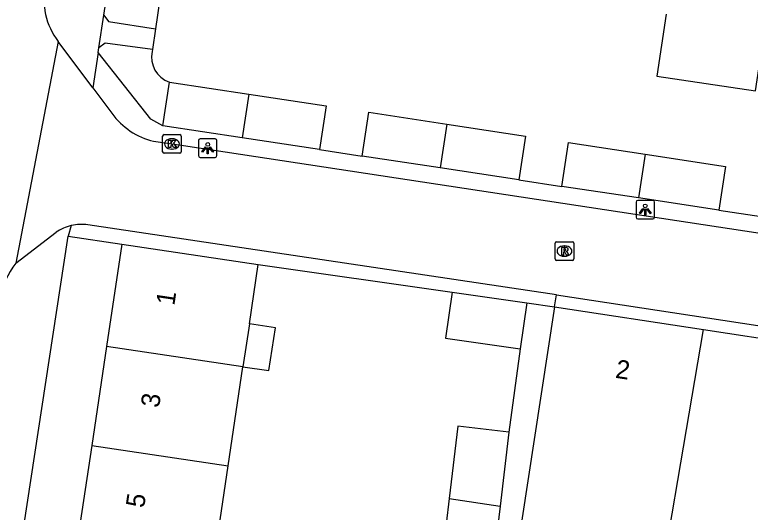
# Model space of a CAD drawing. Extents: x 163010 to 163853, y 382793 to 383982.
# Drawn here: x 163538.3 to 163577.85, y 383156.8 to 383183.57 of the extents above; entities that cross this region are included whole.
import ezdxf

# ---------------------------------------------------------------- set-up
doc = ezdxf.new("R2010")
doc.units = 0
for name, color, linetype in [('IMGEO_Groenvoorziening', 7, 'Continuous'), ('IMGEO_Kolk', 7, 'Continuous'), ('IMGEO_Lichtpunt', 7, 'Continuous'), ('IMGEO_Muur', 7, 'Continuous'), ('IMGEO_Pand', 7, 'Continuous'), ('IMGEO_Pand_nummerreeks', 7, 'Continuous'), ('IMGEO_Rijbaan_lokaal_open', 7, 'Continuous'), ('IMGEO_Rioolput', 7, 'Continuous'), ('IMGEO_Voetpad_open', 7, 'Continuous')]:
    doc.layers.add(name, color=color, linetype=linetype)

msp = doc.modelspace()

# ---------------------------------------------------------------- linework, layer by layer
at = {"layer": 'IMGEO_Groenvoorziening'}
for points in [[(163546.582, 383187.748), (163545.87, 383182.817)], [(163545.709, 383181.698), (163545.693, 383181.587)]]:
    msp.add_lwpolyline(points, dxfattribs=at)
msp.add_arc((163547.06, 383181.277), 1.401, 167.2093, 251.4564, dxfattribs=at)
at = {"layer": 'IMGEO_Kolk'}
for p, q in [((163546.326, 383177.12), (163547.178, 383177.12)), ((163546.251, 383176.194), (163546.251, 383177.046)), ((163546.739, 383176.9), (163546.764, 383176.9)), ((163547.252, 383177.046), (163547.252, 383176.194)), ((163546.762, 383176.34), (163546.737, 383176.34)), ((163547.178, 383176.12), (163546.326, 383176.12))]:
    msp.add_line(p, q, dxfattribs=at)
for points in [[(163546.326, 383177.12), (163547.178, 383177.12)], [(163546.251, 383176.194), (163546.251, 383177.046)], [(163546.572, 383176.82), (163546.695, 383176.82), (163546.695, 383176.669), (163546.825, 383176.82), (163546.989, 383176.82), (163546.843, 383176.669), (163546.996, 383176.42), (163546.844, 383176.42), (163546.759, 383176.584), (163546.695, 383176.517), (163546.695, 383176.42), (163546.572, 383176.42), (163546.572, 383176.82)], [(163547.252, 383177.046), (163547.252, 383176.194)], [(163547.178, 383176.12), (163546.326, 383176.12)]]:
    msp.add_lwpolyline(points, dxfattribs=at)
for centre, start, end in [((163546.328, 383177.044), 91.552, 178.448), ((163546.328, 383177.044), 91.552, 178.448), ((163547.176, 383177.044), 1.552, 88.448), ((163547.176, 383177.044), 1.552, 88.448), ((163546.328, 383176.196), 181.552, 268.448), ((163546.328, 383176.196), 181.552, 268.448), ((163547.176, 383176.196), 271.552, 358.448), ((163547.176, 383176.196), 271.552, 358.448)]:
    msp.add_arc(centre, 0.0765, start, end, dxfattribs=at)
for centre, major_axis, ratio, start_param, end_param in [((163546.738, 383176.62), (-0.387, 0.002), 0.722429, 4.712389, 7.853982), ((163546.763, 383176.62), (-0.39, 0.002), 0.717154, 1.570796, 4.712389)]:
    msp.add_ellipse(centre, major_axis=major_axis, ratio=ratio, start_param=start_param, end_param=end_param, dxfattribs=at)
at = {"layer": 'IMGEO_Lichtpunt'}
for p, q in [((163548.177, 383176.796), (163548.177, 383175.989)), ((163548.177, 383176.796), (163548.177, 383175.989)), ((163549.079, 383176.891), (163548.271, 383176.891)), ((163549.079, 383176.891), (163548.271, 383176.891)), ((163549.173, 383175.989), (163549.173, 383176.796)), ((163549.173, 383175.989), (163549.173, 383176.796)), ((163548.271, 383175.895), (163549.079, 383175.895)), ((163548.271, 383175.895), (163549.079, 383175.895)), ((163572.609, 383173.582), (163571.801, 383173.582)), ((163572.609, 383173.582), (163571.801, 383173.582)), ((163571.707, 383173.487), (163571.707, 383172.68)), ((163571.707, 383173.487), (163571.707, 383172.68)), ((163572.703, 383172.68), (163572.703, 383173.487)), ((163572.703, 383172.68), (163572.703, 383173.487)), ((163571.801, 383172.586), (163572.609, 383172.586)), ((163571.801, 383172.586), (163572.609, 383172.586))]:
    msp.add_line(p, q, dxfattribs=at)
for points in [[(163548.551, 383176.46), (163548.59, 383176.432), (163548.402, 383176.17), (163548.364, 383176.197), (163548.551, 383176.46)], [(163548.653, 383176.412), (163548.7, 383176.412), (163548.7, 383176.09), (163548.653, 383176.09), (163548.653, 383176.412)], [(163548.763, 383176.432), (163548.801, 383176.459), (163548.988, 383176.197), (163548.949, 383176.169), (163548.763, 383176.432)], [(163572.081, 383173.151), (163572.12, 383173.123), (163571.932, 383172.861), (163571.894, 383172.888), (163572.081, 383173.151)], [(163572.293, 383173.123), (163572.331, 383173.15), (163572.518, 383172.888), (163572.479, 383172.86), (163572.293, 383173.123)], [(163572.183, 383173.103), (163572.23, 383173.103), (163572.23, 383172.781), (163572.183, 383172.781), (163572.183, 383173.103)]]:
    msp.add_lwpolyline(points, dxfattribs=at)
for centre in [(163548.676, 383176.594), (163572.206, 383173.285)]:
    msp.add_circle(centre, 0.0994, dxfattribs=at)
for centre, start, end in [((163548.271, 383176.796), 90, 180), ((163548.271, 383176.796), 90, 180), ((163549.079, 383176.796), 0, 90), ((163549.079, 383176.796), 0, 90), ((163548.271, 383175.989), 180, 270), ((163548.271, 383175.989), 180, 270), ((163549.079, 383175.989), 270, 0), ((163549.079, 383175.989), 270, 360), ((163571.801, 383173.487), 90, 180), ((163571.801, 383173.487), 90, 180), ((163572.609, 383173.487), 0, 90), ((163572.609, 383173.487), 0, 90), ((163571.801, 383172.68), 180, 270), ((163571.801, 383172.68), 180, 270), ((163572.609, 383172.68), 270, 0), ((163572.609, 383172.68), 270, 360)]:
    msp.add_arc(centre, 0.0946, start, end, dxfattribs=at)
at = {"layer": 'IMGEO_Muur'}
msp.add_lwpolyline([(163551.396, 383170.138), (163561.824, 383168.644)], dxfattribs=at)
at = {"layer": 'IMGEO_Pand'}
for points in [[(163573.324, 383183.6), (163572.822, 383180.27), (163578.138, 383179.469), (163578.64, 383182.799)], [(163546.258, 383177.595), (163546.614, 383179.948)], [(163546.614, 383179.948), (163550.881, 383179.3)], [(163550.881, 383179.3), (163550.526, 383176.947)], [(163550.881, 383179.3), (163555.039, 383178.669), (163554.681, 383176.317)], [(163556.975, 383175.968), (163557.333, 383178.321), (163561.536, 383177.683)], [(163550.526, 383176.947), (163546.258, 383177.595)], [(163561.536, 383177.683), (163561.181, 383175.33)], [(163561.536, 383177.683), (163565.767, 383177.041), (163565.409, 383174.688)], [(163554.681, 383176.317), (163550.526, 383176.947)], [(163567.712, 383174.339), (163568.07, 383176.691), (163572.191, 383176.066)], [(163561.181, 383175.33), (163556.975, 383175.968)], [(163572.191, 383176.066), (163571.836, 383173.713)], [(163572.191, 383176.066), (163576.523, 383175.409), (163576.165, 383173.056)], [(163565.409, 383174.688), (163561.181, 383175.33)], [(163571.836, 383173.713), (163567.712, 383174.339)], [(163576.165, 383173.056), (163571.836, 383173.713)], [(163544.062, 383171.234), (163543.239, 383165.731)], [(163544.062, 383171.234), (163551.396, 383170.138)], [(163550.917, 383166.934), (163551.396, 383170.138)], [(163561.824, 383168.644), (163561.47, 383166.171), (163565.479, 383165.596)], [(163561.824, 383168.644), (163565.833, 383168.07)], [(163565.833, 383168.07), (163565.479, 383165.596)], [(163567.317, 383167.857), (163564.835, 383151.595), (163572.264, 383148.601)], [(163567.317, 383167.857), (163575.341, 383166.634)], [(163550.917, 383166.934), (163550.573, 383164.635)], [(163550.573, 383164.635), (163551.969, 383164.426), (163552.313, 383166.725), (163550.917, 383166.934)], [(163572.264, 383148.601), (163575.341, 383166.634)], [(163575.341, 383166.634), (163590.125, 383164.381)], [(163543.239, 383165.731), (163542.443, 383160.401)], [(163550.573, 383164.635), (163543.239, 383165.731)], [(163549.777, 383159.305), (163550.573, 383164.635)], [(163564.869, 383161.116), (163562.127, 383161.441), (163561.665, 383157.549)], [(163564.869, 383161.116), (163564.397, 383157.141)], [(163542.443, 383160.401), (163541.646, 383155.072)], [(163542.443, 383160.401), (163549.777, 383159.305)], [(163548.98, 383153.976), (163549.777, 383159.305)], [(163561.665, 383157.549), (163561.18, 383153.465), (163563.922, 383153.139)], [(163561.665, 383157.549), (163564.397, 383157.141)], [(163564.397, 383157.141), (163563.922, 383153.139)]]:
    msp.add_lwpolyline(points, dxfattribs=at)
at = {"layer": 'IMGEO_Rijbaan_lokaal_open'}
for points in [[(163540.639, 383182.128), (163538.367, 383170.199)], [(163542.503, 383179.637), (163540.639, 383182.128)], [(163542.503, 383179.637), (163543.527, 383178.267)], [(163545.77, 383176.763), (163547.368, 383176.527), (163662.219, 383159.074)], [(163567.427, 383168.507), (163542.236, 383172.265)], [(163538.367, 383170.199), (163540.525, 383171.865)], [(163567.427, 383168.507), (163651.335, 383155.72)]]:
    msp.add_lwpolyline(points, dxfattribs=at)
for centre, radius, start, end in [((163543.66, 383184.425), 3.795, 168.4871, 217.2527), ((163546.659, 383180.513), 3.854, 215.6501, 256.6638), ((163541.883, 383169.929), 2.365, 103.2213, 125.0416), ((163541.877, 383169.947), 2.346, 81.1849, 103.171), ((163541.561, 383167.616), 4.108, 141.0286, 170.7761)]:
    msp.add_arc(centre, radius, start, end, dxfattribs=at)
at = {"layer": 'IMGEO_Rioolput'}
for p, q in [((163567.359, 383170.431), (163567.359, 383171.283)), ((163567.434, 383171.357), (163568.286, 383171.357)), ((163568.36, 383171.283), (163568.36, 383170.431)), ((163567.847, 383171.137), (163567.872, 383171.137)), ((163567.87, 383170.577), (163567.845, 383170.577)), ((163568.286, 383170.357), (163567.434, 383170.357))]:
    msp.add_line(p, q, dxfattribs=at)
for points in [[(163567.359, 383170.431), (163567.359, 383171.283)], [(163567.434, 383171.357), (163568.286, 383171.357)], [(163568.36, 383171.283), (163568.36, 383170.431)], [(163567.948, 383171.055), (163567.696, 383171.057), (163567.696, 383170.657)], [(163567.696, 383170.657), (163567.82, 383170.657), (163567.82, 383170.819), (163567.831, 383170.819)], [(163567.874, 383170.976), (163567.82, 383170.976), (163567.82, 383170.895)], [(163567.82, 383170.895), (163567.872, 383170.895)], [(163567.878, 383170.79), (163567.949, 383170.657), (163568.089, 383170.657), (163568.024, 383170.783)], [(163568.286, 383170.357), (163567.434, 383170.357)]]:
    msp.add_lwpolyline(points, dxfattribs=at)
for centre, radius, start, end in [((163567.436, 383171.281), 0.0765, 91.552, 178.448), ((163567.436, 383171.281), 0.0765, 91.552, 178.448), ((163568.284, 383171.281), 0.0765, 1.552, 88.448), ((163568.284, 383171.281), 0.0765, 1.552, 88.448), ((163567.83, 383170.766), 0.0533, 26.0293, 88.6989), ((163567.856, 383171.084), 0.19, 274.7715, 282.9687), ((163567.88, 383170.88), 0.0964, 77.0061, 93.1865), ((163567.894, 383170.937), 0.0378, 276.6634, 79.6772), ((163567.947, 383170.945), 0.109, 350.3612, 89.416), ((163567.945, 383170.945), 0.112, 277.5842, 350.9817), ((163567.929, 383170.73), 0.108, 29.5134, 73.7905), ((163567.436, 383170.433), 0.0765, 181.552, 268.448), ((163567.436, 383170.433), 0.0765, 181.552, 268.448), ((163568.284, 383170.433), 0.0765, 271.552, 358.448), ((163568.284, 383170.433), 0.0765, 271.552, 358.448)]:
    msp.add_arc(centre, radius, start, end, dxfattribs=at)
for centre, major_axis, ratio, start_param, end_param in [((163567.846, 383170.857), (-0.387, 0.002), 0.722429, 4.712389, 7.853982), ((163567.871, 383170.857), (-0.39, 0.002), 0.717154, 1.570796, 4.712389)]:
    msp.add_ellipse(centre, major_axis=major_axis, ratio=ratio, start_param=start_param, end_param=end_param, dxfattribs=at)
at = {"layer": 'IMGEO_Voetpad_open'}
for points in [[(163543.097, 383183.543), (163545.516, 383199.393)], [(163542.828, 383181.785), (163543.097, 383183.543)], [(163543.097, 383183.543), (163543.349, 383183.201), (163545.87, 383182.817)], [(163545.87, 383182.817), (163545.709, 383181.698)], [(163545.709, 383181.698), (163543.165, 383182.037), (163542.828, 383181.785)], [(163542.791, 383181.541), (163542.503, 383179.637)], [(163542.791, 383181.541), (163542.828, 383181.785)], [(163546.258, 383177.595), (163545.615, 383177.956), (163542.791, 383181.541)], [(163554.681, 383176.317), (163556.975, 383175.968)], [(163565.409, 383174.688), (163567.712, 383174.339)], [(163576.165, 383173.056), (163578.439, 383172.712)], [(163541.342, 383172.231), (163541.181, 383171.663)], [(163536.268, 383138.719), (163537.369, 383146.888), (163541.181, 383171.663)], [(163541.181, 383171.663), (163544.062, 383171.234)], [(163551.396, 383170.138), (163561.824, 383168.644)], [(163567.317, 383167.857), (163567.427, 383168.507)], [(163565.833, 383168.07), (163567.317, 383167.857)], [(163565.479, 383165.596), (163564.869, 383161.116)]]:
    msp.add_lwpolyline(points, dxfattribs=at)

# ---------------------------------------------------------------- texts
at = {"layer": 'IMGEO_Pand_nummerreeks'}
for s, rotation, p in [('1', 81.4975, (163546.879, 383167.896)), ('2', 351.4041, (163570.559, 383164.044)), ('3', 81.4978, (163546.057, 383162.395)), ('5', 81.4978, (163545.252, 383157.008))]:
    msp.add_text(s, height=1, rotation=rotation, dxfattribs=at).set_placement(p)

doc.saveas('drawing.dxf')
